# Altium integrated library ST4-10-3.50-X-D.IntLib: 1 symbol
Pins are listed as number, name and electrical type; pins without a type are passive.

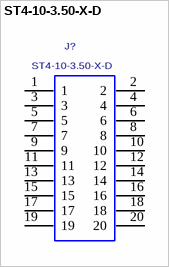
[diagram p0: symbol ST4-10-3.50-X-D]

## ST4-10-3.50-X-D
designator J?
0.4MM TERMINAL STRIP ASSEMBLY, 20 PINS.; MANUFACTURER: SAMTEC
footprint ST4-10-3.50-X-D
pins: 1, 2, 3, 4, 5, 6, 7, 8, 9, 10, 11, 12, 13, 14, 15, 16, 17, 18, 19, 20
